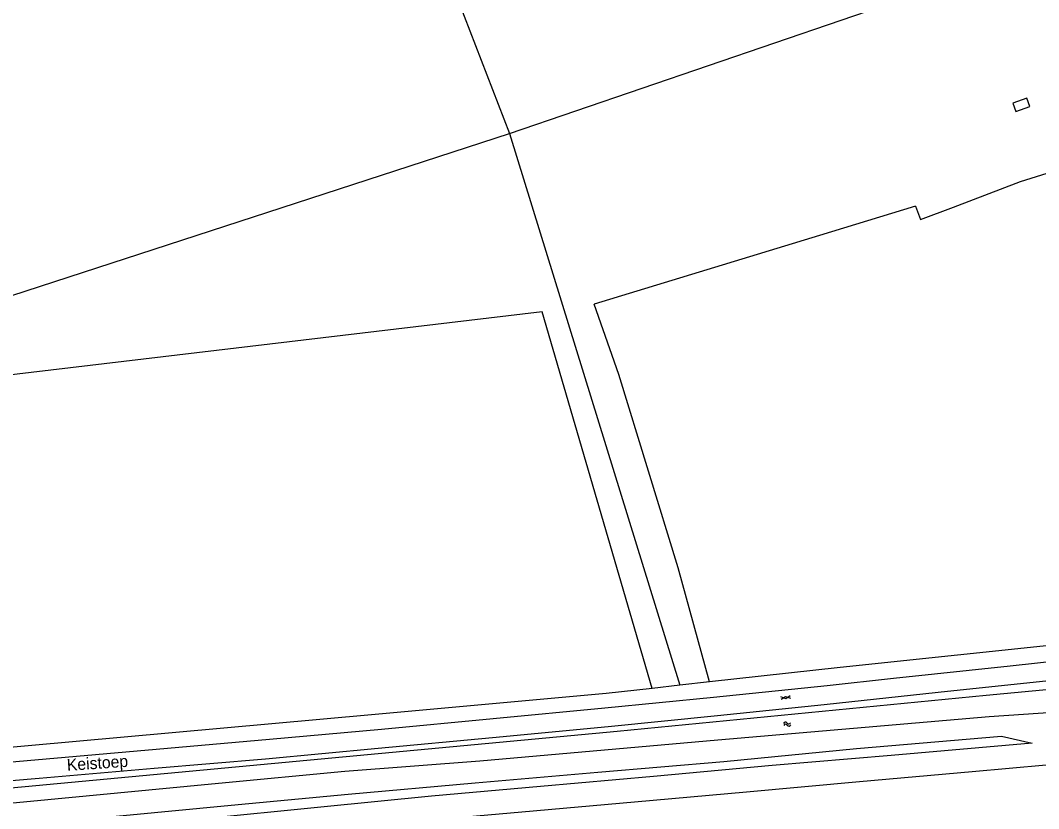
# Model space of a CAD drawing. Extents: x 126000 to 131009, y 393000 to 395500.
# Drawn here: x 129551.5 to 129767.6, y 394560.9 to 394728.2 of the extents above; entities that cross this region are included whole.
import ezdxf

# ---------------------------------------------------------------- set-up
doc = ezdxf.new("R2010")
doc.units = 0
for name, color, linetype in [('gg-anno-openbare ruimte label', 7, 'Continuous'), ('gg-bbg-overig bouwwerk', 7, 'Continuous'), ('gg-knt-BGT kruinlijn', 7, 'Continuous'), ('gg-knt-bronhoudergrens', 7, 'Continuous'), ('gg-knt-verharding', 7, 'Continuous'), ('gg-kntw-bovenkant insteek waterloop', 7, 'Continuous'), ('gt-grn-groengrens', 7, 'Continuous'), ('gt-grn-vlakafsluiter', 7, 'Continuous'), ('gt-symb-gesloten verharding', 7, 'Continuous'), ('gt-symb-watersymbool', 7, 'Continuous'), ('gx-grn-maaiveld', 7, 'Continuous')]:
    doc.layers.add(name, color=color, linetype=linetype)

# ---------------------------------------------------------------- blocks, each defined once
blk = doc.blocks.new('gt0-WA')
at = {"layer": 'gt-symb-watersymbool'}
for centre, start, end in [((-0.32, 0.02), 28.0725, 151.9275), ((0.43, 0.42), 208.0725, 331.9275), ((-0.32, -0.43), 28.0725, 151.9275), ((0.43, -0.03), 208.0725, 331.9275)]:
    blk.add_arc(centre, 0.425, start, end, dxfattribs=at)
blk = doc.blocks.new('gt0-GESVH1')
at = {"layer": 'gt-symb-gesloten verharding'}
for p, q in [((-0.99, -0.26), (0.01, 0.24)), ((0.01, -0.26), (-0.99, 0.24)), ((0.01, 0.24), (1.01, -0.26)), ((1.01, 0.24), (0.01, -0.26))]:
    blk.add_line(p, q, dxfattribs=at)

msp = doc.modelspace()

# ---------------------------------------------------------------- linework, layer by layer
at = {"layer": 'gg-bbg-overig bouwwerk'}
msp.add_lwpolyline([(129765.69, 394709.86), (129765.06, 394711.67), (129762.09, 394710.61), (129762.74, 394708.81), (129765.69, 394709.86)], dxfattribs=at)
at = {"layer": 'gg-knt-BGT kruinlijn'}
for p, q in [((129766.21, 394574.8), (129736.31, 394572.15)), ((129736.31, 394572.15), (129711.01, 394570.04)), ((129711.01, 394570.04), (129685.85, 394567.75)), ((129685.85, 394567.75), (129661.86, 394565.59)), ((129661.86, 394565.59), (129638.73, 394563.54)), ((129638.73, 394563.54), (129615.29, 394561.19)), ((129615.29, 394561.19), (129589.69, 394558.71))]:
    msp.add_line(p, q, dxfattribs=at)
at = {"layer": 'gg-knt-bronhoudergrens'}
for points in [[(129741.44, 394688.71), (129742.51, 394685.9), (129749.48, 394688.55), (129763.73, 394693.98), (129846.04, 394719.71), (129870.97, 394727.24)], [(129741.44, 394688.71), (129721.11, 394682.51), (129673.26, 394667.94)], [(129697.75, 394587.78), (129691.07, 394611.99), (129678.48, 394653.02), (129673.26, 394667.94)]]:
    msp.add_lwpolyline(points, dxfattribs=at)
at = {"layer": 'gg-knt-verharding'}
for points in [[(129543.16, 394570.29), (129556.94, 394571.5), (129580.32, 394573.52), (129604.36, 394575.62), (129628.15, 394577.76), (129651.85, 394580.01), (129675.49, 394582.29), (129698.59, 394584.59), (129722.73, 394587.06), (129736.8, 394588.59), (129761.55, 394591.22), (129785.39, 394593.8), (129802.57, 394595.65)], [(129544.53, 394566.42), (129555.46, 394567.37), (129579.86, 394569.48), (129603.5, 394571.5), (129627.43, 394573.71), (129651.7, 394575.99), (129676.23, 394578.36), (129699.42, 394580.67), (129722.05, 394583.01), (129746.29, 394585.59), (129771.08, 394588.26), (129795.18, 394590.84), (129802.99, 394591.65)]]:
    msp.add_lwpolyline(points, dxfattribs=at)
at = {"layer": 'gg-kntw-bovenkant insteek waterloop'}
msp.add_lwpolyline([(129796.34, 394588.58), (129791.77, 394588.22), (129756.47, 394584.94), (129678.12, 394577.27), (129547.15, 394565.07), (129545.01, 394565.03)], dxfattribs=at)
at = {"layer": 'gt-grn-groengrens'}
for p, q in [((129655.31, 394704.14), (129840.21, 394767.42)), ((129518.28, 394659.59), (129655.31, 394704.14)), ((129655.31, 394704.14), (129691.46, 394587.08)), ((129662.23, 394666.34), (129521.2, 394649.61)), ((129685.6, 394586.43), (129662.23, 394666.34)), ((129691.46, 394587.08), (129685.6, 394586.43)), ((129697.75, 394587.78), (129691.46, 394587.08))]:
    msp.add_line(p, q, dxfattribs=at)
for points in [[(129802.23, 394599.01), (129775.27, 394596.08), (129725.49, 394590.86), (129697.75, 394587.78)], [(129685.6, 394586.43), (129675.84, 394585.35), (129626.01, 394580.8), (129542.11, 394573.27)]]:
    msp.add_lwpolyline(points, dxfattribs=at)
at = {"layer": 'gt-grn-vlakafsluiter'}
msp.add_lwpolyline([(129637.78, 394766.92), (129644.47, 394732.16), (129655.31, 394704.14)], dxfattribs=at)
at = {"layer": 'gx-grn-maaiveld'}
for points in [[(129796.94, 394583.93), (129771.67, 394581.37), (129757.06, 394580.4), (129699.49, 394575.47), (129648.98, 394571), (129620.38, 394568.76), (129593.55, 394566.27), (129550.66, 394562.12), (129549.12, 394562.04), (129547.76, 394562.18), (129547.24, 394562.35), (129546.65, 394561.84), (129545.5, 394559.39)], [(129489.45, 394545.49), (129514.15, 394547.64), (129538.16, 394549.73), (129562.22, 394551.83), (129585.99, 394553.89), (129609.88, 394555.94), (129633.89, 394558.09), (129657.94, 394560.26), (129681.84, 394562.33), (129705.59, 394564.49), (129729.59, 394566.68), (129753.45, 394568.78), (129777, 394570.88), (129801.54, 394573.02), (129825.36, 394575.37), (129849.17, 394577.59), (129862.85, 394578.94)], [(129488.96, 394551.97), (129502.26, 394553.07), (129525.39, 394555.01), (129546.92, 394556.61), (129571.8, 394559.33), (129597.72, 394561.82), (129621.07, 394564), (129647.99, 394566.35), (129674.03, 394568.64), (129700.75, 394570.91), (129728.94, 394573.66), (129759.68, 394576.29), (129766.21, 394574.8)]]:
    msp.add_lwpolyline(points, dxfattribs=at)

# ---------------------------------------------------------------- block references
at = {"layer": 'gt-symb-gesloten verharding', "rotation": 5.334440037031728}
msp.add_blockref('gt0-GESVH1', (129713.88, 394584.49), dxfattribs=at)
at = {"layer": 'gt-symb-watersymbool', "rotation": 5.334440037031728}
msp.add_blockref('gt0-WA', (129714.15, 394578.85), dxfattribs=at)

# ---------------------------------------------------------------- texts
at = {"layer": 'gg-anno-openbare ruimte label'}
msp.add_text('Keistoep', height=2.5, rotation=3.8, dxfattribs=at).set_placement((129561.44, 394568.93))

doc.saveas('drawing.dxf')
